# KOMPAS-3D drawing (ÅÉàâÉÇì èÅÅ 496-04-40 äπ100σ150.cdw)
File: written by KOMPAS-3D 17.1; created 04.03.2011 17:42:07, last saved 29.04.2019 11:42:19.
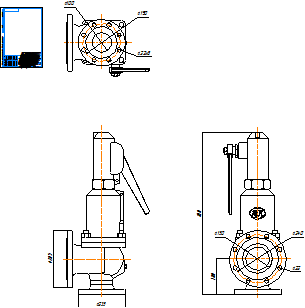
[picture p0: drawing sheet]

Sheet 1: A4, portrait

Title block, sheet 1: name: Прегран Ду 100х150; material: Внимание! Данный продукт является объектом авторского права ООО «Торговый Дом АДЛ». / Запрещается изменение, копирование, распространение / (в том числе путем копирования на другие сайты и ресурсы в Интернете) / или любое иное использование информации и объектов без предварительного / согласия правообладателя (ООО «Торговый Дом АДЛ»).; scale: 1:1; sheets: 1; organisation: ООО "Торговый дом АДЛ"; sheet format: A4; stored path: C:\Users\tra\Desktop\2д чертежи\Предохранительные клапаны ПРЕГРАН\ПРЕГРАН 496\ПРЕГРАН КПП 496-04-40\KOMPAS 2D\Прегран Ду 100х150.cdw

Views: Спереди 1, Проекционный вид 2, Проекционный вид 3
Dimensions and other numbers on the sheet: 235; 285; 180; 810; 240; 22; 150; 190; 100; 1:1; 1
